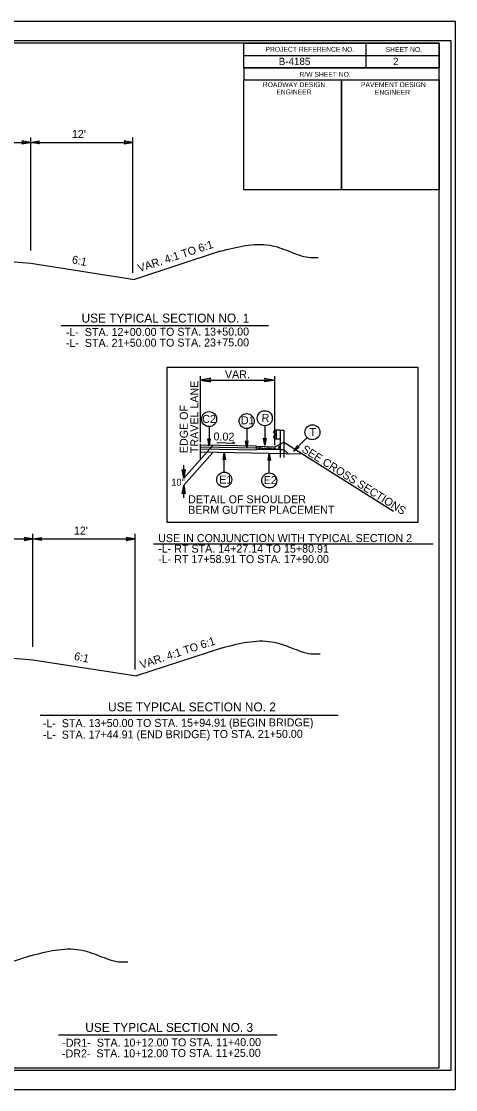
# Model space of a CAD drawing. Extents: x 2532463 to 2534146, y 189689 to 190784.
# Drawn here: x 2533701 to 2534146, y 189689 to 190784 of the extents above; entities that cross this region are included whole.
import ezdxf

# ---------------------------------------------------------------- set-up
doc = ezdxf.new("R2010")
doc.units = 0
for name, color, linetype in [('Old_Level_1', 7, 'Continuous'), ('Old_Level_10', 7, 'Continuous'), ('Old_Level_11', 7, 'Continuous'), ('Old_Level_18', 7, 'Continuous'), ('Old_Level_2', 7, 'Continuous'), ('Old_Level_3', 7, 'Continuous'), ('Old_Level_40', 7, 'Continuous'), ('Old_Level_42', 7, 'Continuous'), ('Old_Level_44', 7, 'Continuous'), ('Old_Level_50', 7, 'Continuous'), ('Old_Level_51', 7, 'Continuous'), ('Old_Level_52', 7, 'Continuous'), ('Typical Curb CELL', 7, 'Continuous'), ('Typical Guardrail CELL', 7, 'Continuous'), ('Typical ID Circle CELL', 7, 'Continuous'), ('Typical Terminator CELL', 7, 'Continuous')]:
    doc.layers.add(name, color=color, linetype=linetype)

msp = doc.modelspace()

# ---------------------------------------------------------------- linework, layer by layer
at = {"layer": 'Old_Level_1'}
for p, q in [((2533632.4, 190542.7), (2533710.9, 190536.4)), ((2533905.2, 190548.6), (2533817.3, 190519.7)), ((2533710.9, 190536.4), (2533817.3, 190519.7)), ((2533742, 190472.4), (2533954.7, 190472.4)), ((2533884.9, 190335.3), (2533884.9, 190351.2)), ((2533942.3, 190348.6), (2533884.9, 190349.8)), ((2533942.2, 190346.6), (2533884.9, 190347.8)), ((2533942.2, 190344.6), (2533884.9, 190345.8)), ((2533942.2, 190344.6), (2533942.2, 190345.3)), ((2533960.9, 190347.9), (2533970.4, 190352.7)), ((2533970.4, 190352.7), (2534082.6, 190282)), ((2533970.4, 190345.3), (2533974.9, 190340.7)), ((2533989.8, 190340.4), (2533884.9, 190342.6)), ((2533634.5, 190136.2), (2533713, 190129.9)), ((2533907.3, 190142.1), (2533819.4, 190113.2)), ((2533713, 190129.9), (2533819.4, 190113.2)), ((2533720.6, 190073), (2534026, 190073)), ((2533710.6, 189826.4), (2533664.9, 189811.4)), ((2533739.4, 189745.3), (2533963.6, 189745.3))]:
    msp.add_line(p, q, dxfattribs=at)
at = {"layer": 'Old_Level_10'}
for points in [[(2533905.2, 190548.6), (2533955.8, 190554.7), (2533975.7, 190548.6), (2533995.7, 190542.4), (2534005.3, 190542.3)], [(2533907.3, 190142.1), (2533957.9, 190148.2), (2533977.9, 190142.1), (2533997.8, 190136), (2534007.4, 190135.8)], [(2533710.6, 189826.4), (2533761.2, 189832.5), (2533781.1, 189826.4), (2533801, 189820.3), (2533810.6, 189820.1)]]:
    msp.add_spline(points, degree=3, dxfattribs=at)
at = {"layer": 'Old_Level_11'}
for p, q in [((2533884.9, 190352.9), (2533884.9, 190420.4)), ((2533884.9, 190416.5), (2533960.9, 190416.5)), ((2533960.9, 190349.8), (2533960.9, 190420.4))]:
    msp.add_line(p, q, dxfattribs=at)
for points in [[(2534107.8, 190429.4), (2533850.4, 190429.4), (2533850.4, 190270.8), (2534107.8, 190270.8)], [(2533895.4, 190418.3), (2533884.9, 190416.5), (2533895.5, 190414.7), (2533894.1, 190416.5)], [(2533950.3, 190418.3), (2533960.9, 190416.5), (2533950.3, 190414.7), (2533951.6, 190416.5)]]:
    msp.add_lwpolyline(points, close=True, dxfattribs=at)
at = {"layer": 'Old_Level_18'}
msp.add_lwpolyline([(2534129.3, 190761.7), (2532629.3, 190761.7), (2532629.3, 189711.7), (2534129.3, 189711.7)], close=True, dxfattribs=at)
at = {"layer": 'Old_Level_2'}
for p, q in [((2533710.9, 190549.4), (2533710.9, 190665.3)), ((2533815.6, 190526.4), (2533815.6, 190665.3)), ((2533599.9, 190660.1), (2533710.8, 190660.1)), ((2533710.8, 190660.1), (2533815.6, 190660.1)), ((2533897.4, 190349.6), (2533867.7, 190316)), ((2533920.2, 190351.6), (2533901.6, 190352)), ((2533920.2, 190351.6), (2533917.9, 190353)), ((2533897.4, 190342.3), (2533867.7, 190308.7)), ((2533867.7, 190316), (2533867.7, 190329.4)), ((2533867.7, 190295.8), (2533867.7, 190308.7)), ((2533713, 190142.9), (2533713, 190258.8)), ((2533817.8, 190119.9), (2533817.8, 190258.8)), ((2533602, 190253.6), (2533713, 190253.6)), ((2533713, 190253.6), (2533817.7, 190253.6)), ((2533836.9, 190248.5), (2534123.2, 190248.5))]:
    msp.add_line(p, q, dxfattribs=at)
at = {"layer": 'Old_Level_3'}
for p, q in [((2533710.8, 190660.1), (2533701.9, 190661.7)), ((2533701.9, 190661.7), (2533703.1, 190660.1)), ((2533710.8, 190660.1), (2533719.7, 190661.7)), ((2533719.7, 190661.7), (2533718.6, 190660.1)), ((2533815.6, 190660.1), (2533806.7, 190661.7)), ((2533806.7, 190661.7), (2533807.8, 190660.1)), ((2533701.9, 190658.6), (2533710.8, 190660.1)), ((2533703.1, 190660.1), (2533701.9, 190658.6)), ((2533719.7, 190658.6), (2533710.8, 190660.1)), ((2533718.6, 190660.1), (2533719.7, 190658.6)), ((2533806.7, 190658.6), (2533815.6, 190660.1)), ((2533807.8, 190660.1), (2533806.7, 190658.6)), ((2533867.7, 190316), (2533866.1, 190324.9)), ((2533866.1, 190324.9), (2533867.7, 190323.7)), ((2533869.3, 190324.9), (2533867.7, 190316)), ((2533867.7, 190323.7), (2533869.3, 190324.9)), ((2533866.1, 190299.8), (2533867.7, 190308.7)), ((2533867.7, 190301), (2533866.1, 190299.8)), ((2533867.7, 190308.7), (2533869.3, 190299.8)), ((2533869.3, 190299.8), (2533867.7, 190301)), ((2533713, 190253.6), (2533704.1, 190255.2)), ((2533704.1, 190255.2), (2533705.2, 190253.6)), ((2533704.1, 190252.1), (2533713, 190253.6)), ((2533705.2, 190253.6), (2533704.1, 190252.1)), ((2533713, 190253.6), (2533721.9, 190255.2)), ((2533721.9, 190252.1), (2533713, 190253.6)), ((2533721.9, 190255.2), (2533720.7, 190253.6)), ((2533720.7, 190253.6), (2533721.9, 190252.1)), ((2533817.7, 190253.6), (2533808.8, 190255.2)), ((2533808.8, 190255.2), (2533810, 190253.6)), ((2533808.8, 190252.1), (2533817.7, 190253.6)), ((2533810, 190253.6), (2533808.8, 190252.1))]:
    msp.add_line(p, q, dxfattribs=at)
at = {"layer": 'Old_Level_40'}
for p, q in [((2534054.3, 190761.6), (2534054.3, 190736.6)), ((2533929.3, 190749.1), (2534129.3, 190749.1)), ((2533929.3, 190736.6), (2534129.3, 190736.6)), ((2533929.3, 190736.6), (2533929.3, 190724.1)), ((2533929.3, 190736.6), (2534129.3, 190736.6)), ((2534029.3, 190724.1), (2534029.3, 190611.7))]:
    msp.add_line(p, q, dxfattribs=at)
for points in [[(2533929.3, 190761.7), (2534129.3, 190761.7), (2534129.3, 190736.6), (2533929.3, 190736.6)], [(2533929.3, 190724.1), (2534029.3, 190724.1), (2534029.3, 190611.6), (2533929.3, 190611.6)], [(2534029.3, 190724.1), (2534129.3, 190724.1), (2534129.3, 190611.6), (2534029.3, 190611.6)]]:
    msp.add_lwpolyline(points, close=True, dxfattribs=at)
at = {"layer": 'Old_Level_50'}
msp.add_line((2534146.3, 190784.2), (2534146.3, 190784.2), dxfattribs=at)
msp.add_lwpolyline([(2532475.8, 189709.2), (2534141.8, 189709.2), (2534141.8, 190764.2), (2532475.8, 190764.2)], close=True, dxfattribs=at)
at = {"layer": 'Old_Level_51'}
msp.add_lwpolyline([(2532462.8, 189689.2), (2534146.3, 189689.2), (2534146.3, 190784.2), (2532462.8, 190784.2)], close=True, dxfattribs=at)
at = {"layer": 'Old_Level_52'}
msp.add_line((2534141.8, 190764.2), (2534141.8, 190764.2), dxfattribs=at)
at = {"layer": 'Typical Curb CELL'}
for p, q in [((2533942.2, 190348.6), (2533942.2, 190348.6)), ((2533942.2, 190345.3), (2533942.2, 190348.5)), ((2533966.4, 190345.3), (2533942.2, 190345.3)), ((2533942.3, 190348.6), (2533960.9, 190347.9)), ((2533944.1, 190346.5), (2533944.8, 190347.5)), ((2533945.1, 190346.5), (2533944.1, 190346.5)), ((2533944.8, 190347.5), (2533945.1, 190346.5)), ((2533950.2, 190346.1), (2533950.7, 190347)), ((2533951.6, 190346.4), (2533950.2, 190346.1)), ((2533950.7, 190347), (2533951.6, 190346.4)), ((2533954.1, 190346.5), (2533954.8, 190347.5)), ((2533955.1, 190346.5), (2533954.1, 190346.5)), ((2533954.8, 190347.5), (2533955.1, 190346.5)), ((2533960.2, 190346.1), (2533960.7, 190347)), ((2533961.6, 190346.4), (2533960.2, 190346.1)), ((2533960.7, 190347), (2533961.6, 190346.4)), ((2533960.9, 190347.9), (2533966.4, 190350.7)), ((2533964.9, 190348), (2533965, 190347.3)), ((2533966.1, 190347.7), (2533964.9, 190348)), ((2533965, 190347.3), (2533966.1, 190347.7)), ((2533966.4, 190345.3), (2533966.4, 190350.7))]:
    msp.add_line(p, q, dxfattribs=at)
for centre in [(2533942.9, 190347.2), (2533943.2, 190348.2), (2533946.2, 190347.6), (2533946.7, 190346.2), (2533947.1, 190345.9), (2533947.4, 190346.9), (2533948, 190346.9), (2533948.4, 190347.1), (2533948.7, 190346.2), (2533950.3, 190346.5), (2533951.9, 190346.4), (2533952.1, 190346.8), (2533952.2, 190347.3), (2533952.6, 190346.1), (2533953.4, 190346.5), (2533954.1, 190346.6), (2533955.1, 190346.2), (2533956.7, 190346.2), (2533957.1, 190345.9), (2533957.4, 190346.9), (2533958.4, 190347.1), (2533958.7, 190346.2), (2533960.3, 190346.5), (2533960.5, 190345.7), (2533961.9, 190346.4), (2533962.1, 190346.8), (2533964.1, 190346.6), (2533965.1, 190346.2), (2533965.9, 190348.4)]:
    msp.add_circle(centre, 0.0642, dxfattribs=at)
msp.add_arc((2533942.3, 190348.5), 0.0833, 87.952, 180, dxfattribs=at)
at = {"layer": 'Typical Guardrail CELL'}
for p, q in [((2533962.4, 190365.2), (2533960.1, 190363.5)), ((2533962.4, 190360.9), (2533960.1, 190362.5)), ((2533962.4, 190360.2), (2533960.1, 190358.5)), ((2533962.4, 190355.9), (2533960.1, 190357.5)), ((2533966.4, 190365.2), (2533962.4, 190365.2)), ((2533962.4, 190365.2), (2533962.4, 190355.9)), ((2533962.4, 190360.5), (2533962.4, 190360.9)), ((2533962.4, 190360.5), (2533962.4, 190360.2)), ((2533966.4, 190355.9), (2533962.4, 190355.9)), ((2533966.4, 190365.2), (2533966.4, 190345.3)), ((2533966.4, 190365.2), (2533970.4, 190365.2)), ((2533970.4, 190365.2), (2533970.4, 190345.3)), ((2533966.4, 190345.3), (2533970.4, 190345.3)), ((2533966.4, 190345.3), (2533966.4, 190337.2)), ((2533970.4, 190345.3), (2533970.4, 190337.2))]:
    msp.add_line(p, q, dxfattribs=at)
for centre, start, end in [((2533960.4, 190363), 125.003, 235.0112), ((2533960.4, 190358), 125.0059, 235.0366)]:
    msp.add_arc(centre, 0.621, start, end, dxfattribs=at)
at = {"layer": 'Typical ID Circle CELL'}
for p, q in [((2533893.7, 190368.8), (2533893.7, 190349)), ((2533932.2, 190366.9), (2533932.2, 190347)), ((2533950.8, 190369.7), (2533950.8, 190349.8)), ((2533994.1, 190357.5), (2533980.1, 190343.5)), ((2533909.2, 190322.1), (2533909.2, 190341.9)), ((2533955.4, 190321.3), (2533955.4, 190341.2))]:
    msp.add_line(p, q, dxfattribs=at)
for centre in [(2533893.7, 190376.5), (2533932.2, 190374.5), (2533950.8, 190377.4), (2533999.6, 190363), (2533909.2, 190314.4), (2533955.4, 190313.6)]:
    msp.add_circle(centre, 7.69, dxfattribs=at)
at = {"layer": 'Typical Terminator CELL'}
for points in [[(2533894.9, 190356.1), (2533893.7, 190349), (2533892.5, 190356.1), (2533893.7, 190355.2)], [(2533952.1, 190356.9), (2533950.8, 190349.8), (2533949.6, 190357), (2533950.8, 190356.1)], [(2533933.4, 190354.1), (2533932.2, 190347), (2533930.9, 190354.1), (2533932.2, 190353.2)], [(2533984.2, 190349.4), (2533980.1, 190343.5), (2533986, 190347.6), (2533984.5, 190347.9)], [(2533908, 190334.8), (2533909.2, 190341.9), (2533910.5, 190334.8), (2533909.2, 190335.7)], [(2533954.1, 190334.1), (2533955.4, 190341.2), (2533956.6, 190334.1), (2533955.4, 190335)]]:
    msp.add_lwpolyline(points, close=True, dxfattribs=at)

# ---------------------------------------------------------------- texts
at = {"layer": 'Old_Level_1'}
for s, height, p in [('TRAVEL LANE', 8.201, (2533882.7, 190341.6)), ('EDGE OF', 8.2, (2533871.9, 190341.6))]:
    msp.add_text(s, height=height, rotation=90, dxfattribs=at).set_placement(p)
at = {"layer": 'Old_Level_11'}
for s, height, p in [('VAR.', 8.2, (2533909.9, 190418.3)), ('DETAIL OF SHOULDER', 8.201, (2533872.3, 190290.2)), ('BERM GUTTER PLACEMENT', 8.201, (2533872.3, 190279.4)), ('USE IN CONJUNCTION WITH TYPICAL SECTION 2', 8.201, (2533841.5, 190250.4)), ('-L- RT STA. 14+27.14 TO 15+80.91', 8.201, (2533841.5, 190239.6)), ('-L- RT 17+58.91 TO STA. 17+90.00  ', 8.201, (2533841.5, 190228.9))]:
    msp.add_text(s, height=height, dxfattribs=at).set_placement(p)
msp.add_text('SEE CROSS SECTIONS', height=8.201, rotation=327.7854, dxfattribs=at).set_placement((2533987.9, 190343.6))
at = {"layer": 'Old_Level_2'}
for s, height, rotation, p in [("12'", 8.2, 0.0001, (2533753.1, 190664.6)), ('6:1', 8.2, 348.1129, (2533752.6, 190536.4)), ('10"', 6.97, 0.0462, (2533855.1, 190308.3)), ("12'", 8.2, 0.0001, (2533755.2, 190258.1)), ('6:1', 8.2, 348.1129, (2533754.8, 190129.9))]:
    msp.add_text(s, height=height, rotation=rotation, dxfattribs=at).set_placement(p)
at = {"layer": 'Old_Level_3'}
for s, height, rotation, p in [('USE TYPICAL SECTION NO. 1', 9.112, 0.0001, (2533763, 190475.5)), ('-L-  STA. 12+00.00 TO STA. 13+50.00', 8.201, 0.2003, (2533746.9, 190461.5)), ('-L-  STA. 21+50.00 TO STA. 23+75.00', 8.201, 0.2003, (2533746.9, 190450.4)), ('C2', 8.2, 359.6908, (2533886.6, 190372.6)), ('D1', 8.2, 359.6908, (2533926.3, 190371.2)), ('R', 8.2, 359.6908, (2533947.5, 190373.7)), ('T', 8.2, 359.6908, (2533996.6, 190359.2)), ('0.02', 8.2, 358.8281, (2533898.2, 190354.7)), ('E1', 8.2, 359.6908, (2533904.1, 190310.4)), ('E2', 8.2, 359.6908, (2533949.6, 190309.9)), ('USE TYPICAL SECTION NO. 2', 9.112, 0.0001, (2533790.2, 190076.9)), ('-L-  STA. 13+50.00 TO STA. 15+94.91 (BEGIN BRIDGE)', 8.201, 0.2003, (2533723.3, 190060.6)), ('-L-  STA. 17+44.91 (END BRIDGE) TO STA. 21+50.00', 8.201, 0.2003, (2533723.3, 190048.9)), ('USE TYPICAL SECTION NO. 3', 9.112, 0.0001, (2533766.8, 189748.4)), ('-DR1-  STA. 10+12.00 TO STA. 11+40.00', 8.201, 0.2003, (2533743.3, 189733.1)), ('-DR2-  STA. 10+12.00 TO STA. 11+25.00', 8.201, 0.2003, (2533743, 189722.1))]:
    msp.add_text(s, height=height, rotation=rotation, dxfattribs=at).set_placement(p)
at = {"layer": 'Old_Level_42'}
for p in [(2533822.3, 190527), (2533824.4, 190120.5)]:
    msp.add_text('VAR. 4:1 TO 6:1', height=8.201, rotation=18.2581, dxfattribs=at).set_placement(p)
at = {"layer": 'Old_Level_44'}
for s, height, p in [('PROJECT REFERENCE NO.', 5, (2533951.5, 190753)), ('SHEET NO.', 5, (2534074.6, 190752.9)), ('B-4185   ', 7.5, (2533965.1, 190739.4)), ('2  ', 7.5, (2534082.2, 190739.4)), ('R/W SHEET NO.', 5, (2533986.3, 190727.4)), ('ROADWAY DESIGN', 5, (2533948.7, 190716.8)), ('PAVEMENT DESIGN', 5, (2534049.3, 190716.8)), ('ENGINEER', 5, (2533962.6, 190709.3)), ('ENGINEER', 5, (2534063.6, 190708.9))]:
    msp.add_text(s, height=height, dxfattribs=at).set_placement(p)

doc.saveas('drawing.dxf')
